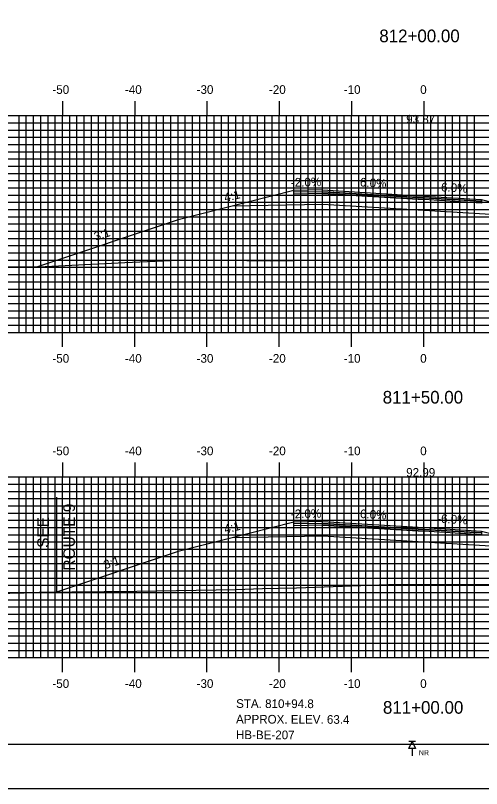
# Model space of a CAD drawing. Extents: x 2059 to 2403, y -1658 to -1438.
# Drawn here: x 2168.7 to 2233.2, y -1657.7 to -1550.7 of the extents above; entities that cross this region are included whole.
import ezdxf

# ---------------------------------------------------------------- set-up
doc = ezdxf.new("R2010")
doc.units = 0
for name, color, linetype in [('ANNOTATION', 7, 'Continuous'), ('BORDER', 7, 'Continuous'), ('BORING - NO REFUSAL', 7, 'Continuous'), ('D_Roadway_Centerline_Text', 7, 'Continuous'), ('D_Roadway_Edge_Shoulder', 7, 'Continuous'), ('D_Roadway_Edge_TW', 7, 'Continuous'), ('D_Roadway_Pavement', 7, 'Continuous'), ('D_Roadway_SlopeLines', 7, 'Continuous'), ('D_Roadway_SubGrade', 7, 'Continuous'), ('H_V ANNOTATION', 7, 'Continuous'), ('MAJOR', 7, 'Continuous'), ('MINOR', 7, 'Continuous'), ('PLOT BOUNDARY', 7, 'Continuous'), ('S_Roadway_Centerline', 7, 'Continuous')]:
    doc.layers.add(name, color=color, linetype=linetype)

msp = doc.modelspace()

# ---------------------------------------------------------------- linework, layer by layer
at = {"layer": 'ANNOTATION'}
for p, q in [((2211.19, -1574.89), (2207.19, -1574.97)), ((2211.19, -1575.14), (2207.19, -1575.22)), ((2211.19, -1576.89), (2198.68, -1577.14)), ((2211.19, -1620.78), (2207.19, -1620.86)), ((2211.19, -1621.03), (2207.19, -1621.11)), ((2211.19, -1622.78), (2198.68, -1623.03))]:
    msp.add_line(p, q, dxfattribs=at)
for points in [[(2211.19, -1575.39), (2207.19, -1575.47), (2207.19, -1574.97)], [(2207.19, -1620.86), (2191.19, -1624.94), (2174.38, -1630.54)], [(2211.19, -1621.28), (2207.19, -1621.36), (2207.19, -1620.86)]]:
    msp.add_lwpolyline(points, dxfattribs=at)
at = {"layer": 'BORDER'}
msp.add_lwpolyline([(2075.59, -1651.6), (2395.59, -1651.6), (2395.59, -1441.6), (2075.59, -1441.6)], close=True, dxfattribs=at)
at = {"layer": 'BORING - NO REFUSAL'}
for p, q in [((2224.07, -1651.2), (2223.11, -1651.2)), ((2223.59, -1652.16), (2223.59, -1653.22))]:
    msp.add_line(p, q, dxfattribs=at)
msp.add_lwpolyline([(2223.59, -1651.2), (2224.07, -1652.16), (2223.11, -1652.16)], close=True, dxfattribs=at)
at = {"layer": 'D_Roadway_Edge_Shoulder'}
for points in [[(2225.19, -1575.73), (2233.19, -1576.21), (2233.19, -1576.46), (2225.19, -1575.98)], [(2225.19, -1575.98), (2233.19, -1576.46), (2233.19, -1576.71), (2225.19, -1576.23)], [(2225.19, -1621.62), (2233.19, -1622.1), (2233.19, -1622.35), (2225.19, -1621.87)], [(2225.19, -1621.87), (2233.19, -1622.35), (2233.19, -1622.6), (2225.19, -1622.12)]]:
    msp.add_lwpolyline(points, close=True, dxfattribs=at)
at = {"layer": 'D_Roadway_Edge_TW'}
for points in [[(2211.19, -1574.89), (2225.19, -1575.73), (2225.19, -1575.98), (2211.19, -1575.14)], [(2211.19, -1620.78), (2225.19, -1621.62), (2225.19, -1621.87), (2211.19, -1621.03)]]:
    msp.add_lwpolyline(points, close=True, dxfattribs=at)
at = {"layer": 'D_Roadway_Pavement'}
for points in [[(2211.19, -1575.14), (2225.19, -1575.98), (2225.19, -1576.23), (2211.19, -1575.39)], [(2211.19, -1621.03), (2225.19, -1621.87), (2225.19, -1622.12), (2211.19, -1621.28)]]:
    msp.add_lwpolyline(points, close=True, dxfattribs=at)
for points in [[(2225.19, -1575.98), (2225.19, -1576.23)], [(2225.19, -1575.98), (2225.19, -1576.23)], [(2225.19, -1621.87), (2225.19, -1622.12)], [(2225.19, -1621.87), (2225.19, -1622.12)]]:
    msp.add_lwpolyline(points, dxfattribs=at)
at = {"layer": 'D_Roadway_SlopeLines'}
for points in [[(2233.19, -1576.21), (2265.57, -1584.31)], [(2233.19, -1622.1), (2261.54, -1629.19)]]:
    msp.add_lwpolyline(points, dxfattribs=at)
at = {"layer": 'D_Roadway_SubGrade'}
msp.add_line((2174.38, -1617.4), (2174.38, -1630.54), dxfattribs=at)
msp.add_lwpolyline([(2207.19, -1574.97), (2191.19, -1579.05), (2171.72, -1585.54)], dxfattribs=at)
for points in [[(2211.19, -1575.39), (2225.19, -1576.23), (2225.19, -1577.73), (2211.19, -1576.89)], [(2225.19, -1576.23), (2225.19, -1575.98), (2233.19, -1576.46), (2233.19, -1576.21), (2243.71, -1578.85), (2225.19, -1577.73)], [(2211.19, -1621.28), (2225.19, -1622.12), (2225.19, -1623.62), (2211.19, -1622.78)], [(2225.19, -1622.12), (2225.19, -1621.87), (2233.19, -1622.35), (2233.19, -1622.1), (2243.71, -1624.73), (2225.19, -1623.62)]]:
    msp.add_lwpolyline(points, close=True, dxfattribs=at)
at = {"layer": 'MAJOR'}
for p, q in [((2175.19, -1562.6), (2175.19, -1564.6)), ((2185.19, -1562.6), (2185.19, -1564.6)), ((2195.19, -1562.6), (2195.19, -1564.6)), ((2205.19, -1562.6), (2205.19, -1564.6)), ((2215.19, -1562.6), (2215.19, -1564.6)), ((2225.19, -1562.6), (2225.19, -1564.6)), ((2085.19, -1564.6), (2365.19, -1564.6)), ((2085.19, -1564.6), (2365.19, -1564.6)), ((2175.19, -1594.6), (2175.19, -1564.6)), ((2185.19, -1594.6), (2185.19, -1564.6)), ((2195.19, -1594.6), (2195.19, -1564.6)), ((2205.19, -1594.6), (2205.19, -1564.6)), ((2215.19, -1594.6), (2215.19, -1564.6)), ((2225.19, -1594.6), (2225.19, -1564.6)), ((2085.19, -1569.6), (2365.19, -1569.6)), ((2085.19, -1574.6), (2365.19, -1574.6)), ((2085.19, -1579.6), (2365.19, -1579.6)), ((2085.19, -1584.6), (2365.19, -1584.6)), ((2085.19, -1589.6), (2365.19, -1589.6)), ((2085.19, -1594.6), (2365.19, -1594.6)), ((2085.19, -1594.6), (2365.19, -1594.6)), ((2175.19, -1596.61), (2175.19, -1594.6)), ((2185.19, -1596.61), (2185.19, -1594.6)), ((2195.19, -1596.61), (2195.19, -1594.6)), ((2205.19, -1596.61), (2205.19, -1594.6)), ((2215.19, -1596.61), (2215.19, -1594.6)), ((2225.19, -1596.61), (2225.19, -1594.6)), ((2175.19, -1612.6), (2175.19, -1614.6)), ((2185.19, -1612.6), (2185.19, -1614.6)), ((2195.19, -1612.6), (2195.19, -1614.6)), ((2205.19, -1612.6), (2205.19, -1614.6)), ((2215.19, -1612.6), (2215.19, -1614.6)), ((2225.19, -1612.6), (2225.19, -1614.6)), ((2085.19, -1614.6), (2365.19, -1614.6)), ((2085.19, -1614.6), (2365.19, -1614.6)), ((2175.19, -1639.6), (2175.19, -1614.6)), ((2185.19, -1639.6), (2185.19, -1614.6)), ((2195.19, -1639.6), (2195.19, -1614.6)), ((2205.19, -1639.6), (2205.19, -1614.6)), ((2215.19, -1639.6), (2215.19, -1614.6)), ((2225.19, -1639.6), (2225.19, -1614.6)), ((2085.19, -1619.6), (2365.19, -1619.6)), ((2085.19, -1624.6), (2365.19, -1624.6)), ((2085.19, -1629.6), (2365.19, -1629.6)), ((2085.19, -1634.6), (2365.19, -1634.6)), ((2085.19, -1639.6), (2365.19, -1639.6)), ((2085.19, -1639.6), (2365.19, -1639.6)), ((2175.19, -1641.61), (2175.19, -1639.6)), ((2185.19, -1641.61), (2185.19, -1639.6)), ((2195.19, -1641.61), (2195.19, -1639.6)), ((2205.19, -1641.61), (2205.19, -1639.6)), ((2215.19, -1641.61), (2215.19, -1639.6)), ((2225.19, -1641.61), (2225.19, -1639.6))]:
    msp.add_line(p, q, dxfattribs=at)
at = {"layer": 'MINOR'}
for p, q in [((2169.19, -1594.6), (2169.19, -1564.6)), ((2170.19, -1594.6), (2170.19, -1564.6)), ((2171.19, -1594.6), (2171.19, -1564.6)), ((2172.19, -1594.6), (2172.19, -1564.6)), ((2173.19, -1594.6), (2173.19, -1564.6)), ((2174.19, -1594.6), (2174.19, -1564.6)), ((2176.19, -1594.6), (2176.19, -1564.6)), ((2177.19, -1594.6), (2177.19, -1564.6)), ((2178.19, -1594.6), (2178.19, -1564.6)), ((2179.19, -1594.6), (2179.19, -1564.6)), ((2180.19, -1594.6), (2180.19, -1564.6)), ((2181.19, -1594.6), (2181.19, -1564.6)), ((2182.19, -1594.6), (2182.19, -1564.6)), ((2183.19, -1594.6), (2183.19, -1564.6)), ((2184.19, -1594.6), (2184.19, -1564.6)), ((2186.19, -1594.6), (2186.19, -1564.6)), ((2187.19, -1594.6), (2187.19, -1564.6)), ((2188.19, -1594.6), (2188.19, -1564.6)), ((2189.19, -1594.6), (2189.19, -1564.6)), ((2190.19, -1594.6), (2190.19, -1564.6)), ((2191.19, -1594.6), (2191.19, -1564.6)), ((2192.19, -1594.6), (2192.19, -1564.6)), ((2193.19, -1594.6), (2193.19, -1564.6)), ((2194.19, -1594.6), (2194.19, -1564.6)), ((2196.19, -1594.6), (2196.19, -1564.6)), ((2197.19, -1594.6), (2197.19, -1564.6)), ((2198.19, -1594.6), (2198.19, -1564.6)), ((2199.19, -1594.6), (2199.19, -1564.6)), ((2200.19, -1594.6), (2200.19, -1564.6)), ((2201.19, -1594.6), (2201.19, -1564.6)), ((2202.19, -1594.6), (2202.19, -1564.6)), ((2203.19, -1594.6), (2203.19, -1564.6)), ((2204.19, -1594.6), (2204.19, -1564.6)), ((2206.19, -1594.6), (2206.19, -1564.6)), ((2207.19, -1594.6), (2207.19, -1564.6)), ((2208.19, -1594.6), (2208.19, -1564.6)), ((2209.19, -1594.6), (2209.19, -1564.6)), ((2210.19, -1594.6), (2210.19, -1564.6)), ((2211.19, -1594.6), (2211.19, -1564.6)), ((2212.19, -1594.6), (2212.19, -1564.6)), ((2213.19, -1594.6), (2213.19, -1564.6)), ((2214.19, -1594.6), (2214.19, -1564.6)), ((2216.19, -1594.6), (2216.19, -1564.6)), ((2217.19, -1594.6), (2217.19, -1564.6)), ((2218.19, -1594.6), (2218.19, -1564.6)), ((2219.19, -1594.6), (2219.19, -1564.6)), ((2220.19, -1594.6), (2220.19, -1564.6)), ((2221.19, -1594.6), (2221.19, -1564.6)), ((2222.19, -1594.6), (2222.19, -1564.6)), ((2223.19, -1594.6), (2223.19, -1564.6)), ((2224.19, -1594.6), (2224.19, -1564.6)), ((2226.19, -1594.6), (2226.19, -1564.6)), ((2227.19, -1594.6), (2227.19, -1564.6)), ((2228.19, -1594.6), (2228.19, -1564.6)), ((2229.19, -1594.6), (2229.19, -1564.6)), ((2230.19, -1594.6), (2230.19, -1564.6)), ((2231.19, -1594.6), (2231.19, -1564.6)), ((2232.19, -1594.6), (2232.19, -1564.6)), ((2085.19, -1565.6), (2365.19, -1565.6)), ((2085.19, -1566.6), (2365.19, -1566.6)), ((2085.19, -1567.6), (2365.19, -1567.6)), ((2085.19, -1568.6), (2365.19, -1568.6)), ((2085.19, -1570.6), (2365.19, -1570.6)), ((2085.19, -1571.6), (2365.19, -1571.6)), ((2085.19, -1572.6), (2365.19, -1572.6)), ((2085.19, -1573.6), (2365.19, -1573.6)), ((2085.19, -1575.6), (2365.19, -1575.6)), ((2085.19, -1576.6), (2365.19, -1576.6)), ((2085.19, -1577.6), (2365.19, -1577.6)), ((2085.19, -1578.6), (2365.19, -1578.6)), ((2085.19, -1580.6), (2365.19, -1580.6)), ((2085.19, -1581.6), (2365.19, -1581.6)), ((2085.19, -1582.6), (2365.19, -1582.6)), ((2085.19, -1583.6), (2365.19, -1583.6)), ((2085.19, -1585.6), (2365.19, -1585.6)), ((2085.19, -1586.6), (2365.19, -1586.6)), ((2085.19, -1587.6), (2365.19, -1587.6)), ((2085.19, -1588.6), (2365.19, -1588.6)), ((2085.19, -1590.6), (2365.19, -1590.6)), ((2085.19, -1591.6), (2365.19, -1591.6)), ((2085.19, -1592.6), (2365.19, -1592.6)), ((2085.19, -1593.6), (2365.19, -1593.6)), ((2169.19, -1639.6), (2169.19, -1614.6)), ((2170.19, -1639.6), (2170.19, -1614.6)), ((2171.19, -1639.6), (2171.19, -1614.6)), ((2172.19, -1639.6), (2172.19, -1614.6)), ((2173.19, -1639.6), (2173.19, -1614.6)), ((2174.19, -1639.6), (2174.19, -1614.6)), ((2176.19, -1639.6), (2176.19, -1614.6)), ((2177.19, -1639.6), (2177.19, -1614.6)), ((2178.19, -1639.6), (2178.19, -1614.6)), ((2179.19, -1639.6), (2179.19, -1614.6)), ((2180.19, -1639.6), (2180.19, -1614.6)), ((2181.19, -1639.6), (2181.19, -1614.6)), ((2182.19, -1639.6), (2182.19, -1614.6)), ((2183.19, -1639.6), (2183.19, -1614.6)), ((2184.19, -1639.6), (2184.19, -1614.6)), ((2186.19, -1639.6), (2186.19, -1614.6)), ((2187.19, -1639.6), (2187.19, -1614.6)), ((2188.19, -1639.6), (2188.19, -1614.6)), ((2189.19, -1639.6), (2189.19, -1614.6)), ((2190.19, -1639.6), (2190.19, -1614.6)), ((2191.19, -1639.6), (2191.19, -1614.6)), ((2192.19, -1639.6), (2192.19, -1614.6)), ((2193.19, -1639.6), (2193.19, -1614.6)), ((2194.19, -1639.6), (2194.19, -1614.6)), ((2196.19, -1639.6), (2196.19, -1614.6)), ((2197.19, -1639.6), (2197.19, -1614.6)), ((2198.19, -1639.6), (2198.19, -1614.6)), ((2199.19, -1639.6), (2199.19, -1614.6)), ((2200.19, -1639.6), (2200.19, -1614.6)), ((2201.19, -1639.6), (2201.19, -1614.6)), ((2202.19, -1639.6), (2202.19, -1614.6)), ((2203.19, -1639.6), (2203.19, -1614.6)), ((2204.19, -1639.6), (2204.19, -1614.6)), ((2206.19, -1639.6), (2206.19, -1614.6)), ((2207.19, -1639.6), (2207.19, -1614.6)), ((2208.19, -1639.6), (2208.19, -1614.6)), ((2209.19, -1639.6), (2209.19, -1614.6)), ((2210.19, -1639.6), (2210.19, -1614.6)), ((2211.19, -1639.6), (2211.19, -1614.6)), ((2212.19, -1639.6), (2212.19, -1614.6)), ((2213.19, -1639.6), (2213.19, -1614.6)), ((2214.19, -1639.6), (2214.19, -1614.6)), ((2216.19, -1639.6), (2216.19, -1614.6)), ((2217.19, -1639.6), (2217.19, -1614.6)), ((2218.19, -1639.6), (2218.19, -1614.6)), ((2219.19, -1639.6), (2219.19, -1614.6)), ((2220.19, -1639.6), (2220.19, -1614.6)), ((2221.19, -1639.6), (2221.19, -1614.6)), ((2222.19, -1639.6), (2222.19, -1614.6)), ((2223.19, -1639.6), (2223.19, -1614.6)), ((2224.19, -1639.6), (2224.19, -1614.6)), ((2226.19, -1639.6), (2226.19, -1614.6)), ((2227.19, -1639.6), (2227.19, -1614.6)), ((2228.19, -1639.6), (2228.19, -1614.6)), ((2229.19, -1639.6), (2229.19, -1614.6)), ((2230.19, -1639.6), (2230.19, -1614.6)), ((2231.19, -1639.6), (2231.19, -1614.6)), ((2232.19, -1639.6), (2232.19, -1614.6)), ((2085.19, -1615.6), (2365.19, -1615.6)), ((2085.19, -1616.6), (2365.19, -1616.6)), ((2085.19, -1617.6), (2365.19, -1617.6)), ((2085.19, -1618.6), (2365.19, -1618.6)), ((2085.19, -1620.6), (2365.19, -1620.6)), ((2085.19, -1621.6), (2365.19, -1621.6)), ((2085.19, -1622.6), (2365.19, -1622.6)), ((2085.19, -1623.6), (2365.19, -1623.6)), ((2085.19, -1625.6), (2365.19, -1625.6)), ((2085.19, -1626.6), (2365.19, -1626.6)), ((2085.19, -1627.6), (2365.19, -1627.6)), ((2085.19, -1628.6), (2365.19, -1628.6)), ((2085.19, -1630.6), (2365.19, -1630.6)), ((2085.19, -1631.6), (2365.19, -1631.6)), ((2085.19, -1632.6), (2365.19, -1632.6)), ((2085.19, -1633.6), (2365.19, -1633.6)), ((2085.19, -1635.6), (2365.19, -1635.6)), ((2085.19, -1636.6), (2365.19, -1636.6)), ((2085.19, -1637.6), (2365.19, -1637.6)), ((2085.19, -1638.6), (2365.19, -1638.6))]:
    msp.add_line(p, q, dxfattribs=at)
at = {"layer": 'PLOT BOUNDARY'}
msp.add_lwpolyline([(2059.4, -1657.72), (2399.4, -1657.72), (2399.4, -1437.72), (2059.4, -1437.72)], close=True, dxfattribs=at)
at = {"layer": 'S_Roadway_Centerline'}
for points in [[(2155.58, -1585.48), (2171.86, -1585.54), (2183.8, -1584.91), (2191.16, -1584.63), (2200.71, -1584.67), (2204.03, -1584.7), (2204.99, -1584.67), (2207.3, -1584.66), (2223.45, -1584.5), (2229.59, -1584.56), (2240.77, -1584.4), (2247.61, -1584.49), (2257.78, -1584.56), (2267.55, -1584.25), (2275.14, -1584.38), (2280.43, -1584.34)], [(2165.86, -1630.74), (2169.87, -1630.62), (2171.98, -1630.57), (2185.47, -1630.4), (2199.17, -1630.2), (2202.88, -1630.06), (2207.59, -1629.97), (2220.32, -1629.49), (2228.8, -1629.48), (2237.12, -1629.51), (2243.9, -1629.19), (2252.38, -1629.15), (2254.15, -1629.29), (2256.97, -1629.24), (2271.79, -1629.07), (2272.13, -1629.07), (2287.23, -1628.99)]]:
    msp.add_lwpolyline(points, dxfattribs=at)

# ---------------------------------------------------------------- texts
at = {"layer": 'ANNOTATION'}
for s, height, rotation, p in [('-2.0%', 1.2, 1.1458, (2206.82, -1574.45)), ('6.0%', 1.2, 356.5664, (2216.34, -1574.4)), ('-6.0%', 1.2, 356.5664, (2227.02, -1575.04)), ('4:1', 1.2, 14.0362, (2197.72, -1576.56)), ('3:1', 1.2, 18.4348, (2179.79, -1581.94)), ('ROUTE 9', 1.6, 90, (2176.91, -1627.57)), ('-2.0%', 1.2, 1.1458, (2206.82, -1620.33)), ('6.0%', 1.2, 356.5664, (2216.34, -1620.28)), ('SEE', 1.6, 90, (2173.31, -1624.42)), ('-6.0%', 1.2, 356.5664, (2227.02, -1620.92)), ('4:1', 1.2, 14.0362, (2197.72, -1622.44)), ('3:1', 1.2, 18.4348, (2181.12, -1627.38))]:
    msp.add_text(s, height=height, rotation=rotation, dxfattribs=at).set_placement(p)
at = {"layer": 'BORING - NO REFUSAL'}
for s, p in [('STA. 810+94.8', (2199.22, -1646.56)), ('APPROX. ELEV. 63.4', (2199.21, -1648.72)), ('HB-BE-207', (2199.2, -1650.88))]:
    msp.add_text(s, height=1.2, rotation=359.8142, dxfattribs=at).set_placement(p)
msp.add_text('NR', height=0.7, dxfattribs=at).set_placement((2224.52, -1653.12))
at = {"layer": 'D_Roadway_Centerline_Text'}
for s, p in [('93.87', (2222.76, -1565.71)), ('92.99', (2222.76, -1614.58))]:
    msp.add_text(s, height=1.2, dxfattribs=at).set_placement(p)
at = {"layer": 'H_V ANNOTATION'}
for s, height, p in [('812+00.00', 1.75, (2219.04, -1554.45)), ('-50', 1.2, (2173.8, -1561.6)), ('-40', 1.2, (2183.84, -1561.6)), ('-30', 1.2, (2193.76, -1561.6)), ('-20', 1.2, (2203.77, -1561.6)), ('-10', 1.2, (2214.12, -1561.6)), ('0', 1.2, (2224.7, -1561.6)), ('-50', 1.2, (2173.8, -1598.8)), ('-40', 1.2, (2183.84, -1598.8)), ('-30', 1.2, (2193.76, -1598.8)), ('-20', 1.2, (2203.77, -1598.8)), ('-10', 1.2, (2214.12, -1598.8)), ('0', 1.2, (2224.7, -1598.8)), ('811+50.00', 1.75, (2219.51, -1604.45)), ('-50', 1.2, (2173.8, -1611.6)), ('-40', 1.2, (2183.84, -1611.6)), ('-30', 1.2, (2193.76, -1611.6)), ('-20', 1.2, (2203.77, -1611.6)), ('-10', 1.2, (2214.12, -1611.6)), ('0', 1.2, (2224.7, -1611.6)), ('-50', 1.2, (2173.8, -1643.8)), ('-40', 1.2, (2183.84, -1643.8)), ('-30', 1.2, (2193.76, -1643.8)), ('-20', 1.2, (2203.77, -1643.8)), ('-10', 1.2, (2214.12, -1643.8)), ('0', 1.2, (2224.7, -1643.8)), ('811+00.00', 1.75, (2219.54, -1647.37))]:
    msp.add_text(s, height=height, dxfattribs=at).set_placement(p)

doc.saveas('drawing.dxf')
